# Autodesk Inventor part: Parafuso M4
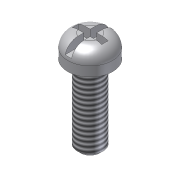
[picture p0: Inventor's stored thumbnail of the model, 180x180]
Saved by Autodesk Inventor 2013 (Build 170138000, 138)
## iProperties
Created: 2010-06
Part Number: Parafuso M4
Document SubType Name: Modeling
Designer: Usuario
Density: 1 g/cm^3
Material: Genérico
Mass: 0.253533 g
Surface Area: 3.0618 cm^2
Volume: 0.253533 cm^3
Author: Usuario
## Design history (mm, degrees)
sketch "Sketch1"
  geometry: C1 r 2 at (0, 0); 1 further point
  constraints: 1 centre point, 1 coincident
  dimensions: "d0" = 4 diameter of C1
extrude "Extrusion1" new body sketch "Sketch1" distance "d1" = 12; taper "d2" = 0 deg
sketch "Sketch2"
  geometry: C1 r 2 at (0, 0) reference; C2 r 3.5 at (0, 0)
  constraints: 1 centre point, 1 coincident
  dimensions: "d3" = 7 diameter of C2
extrude "Extrusion2" join sketch "Sketch2" distance "d4" = 3.5; taper "d5" = 0 deg
fillet "Fillet1" dims "d6" = 2
chamfer "Chamfer1" distance "d7" = 0.5; stored, may be unused: second distance "d8" = 2, angle "d9" = 45 deg
sketch "Sketch3"
  geometry: L1 (-0.5, -0.5)-(-2.3, -0.5); L2 (-2.3, -0.5)-(-2.3, 0.001); L3 (-2.3, 0.001)-(-0.5, 0.001); L4 (-0.5, 0.502)-(-2.3, 0.502); L5 (-2.3, 0.502)-(-2.3, 0.001); L6 (0.5, -0.5)-(2.3, -0.5); L7 (2.3, -0.5)-(2.3, 0.001); L8 (2.3, 0.001)-(0.5, 0.001); L9 (0.5, 0.502)-(2.3, 0.502); L10 (2.3, 0.502)-(2.3, 0.001); L11 (-0.5, 4.357)-(0.5, 4.357); L12 (-0.5, -4.356)-(0.5, -4.356); L13 (0.5, -4.356)-(0.5, -0.5); L14 (0.5, 0.502)-(0.5, 4.357); L15 (-0.5, -4.356)-(-0.5, -0.5); L16 (-0.5, 0.502)-(-0.5, 4.357); C1 r 1.5 at (0, 0) reference
  constraints: 32 end point, 4 perpendicular, 2 symmetric about line, 1 parallel
  dimensions: "d11" = 0.5 distance from line of C1.centre L1; "d12" = 1.8 distance of L1.start L1.end
extrude "Extrusion3" cut sketch "Sketch3" distance "d13" = 1.5; taper "d14" = 0 deg
thread "Thread1" dims "d15" = 10, "d16" = 0
body "Solid1"
